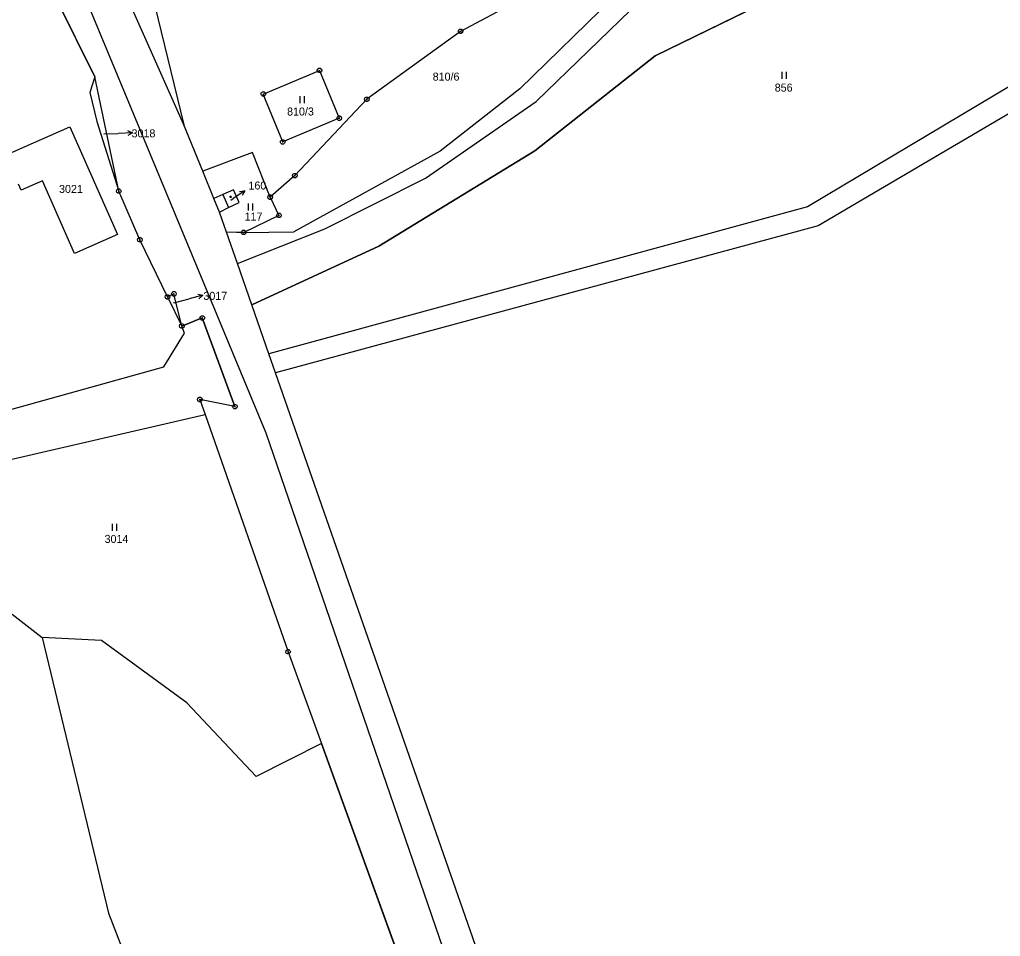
# Model space of a CAD drawing. Extents: x -580551 to -575069, y -1073031 to -1067931.
# Drawn here: x -578349.8 to -578141.5, y -1072489.2 to -1072294.4 of the extents above; entities that cross this region are included whole.
import ezdxf

# ---------------------------------------------------------------- set-up
doc = ezdxf.new("R2010")
doc.units = 0
for name, color, linetype in [('Druh pozemku', 7, 'Continuous'), ('Geodetické body', 7, 'Continuous'), ('Hranice okresů', 7, 'Continuous'), ('Hranice z DKM', 7, 'Continuous'), ('Parcela', 7, 'Continuous'), ('Parcelní číslo', 7, 'Continuous'), ('Parcelní číslo_stavba', 7, 'Continuous'), ('Pomocná vrstva', 7, 'Continuous'), ('Vnitřní kresba', 7, 'Continuous'), ('Vrstva 6', 7, 'Continuous')]:
    doc.layers.add(name, color=color, linetype=linetype)

msp = doc.modelspace()

# ---------------------------------------------------------------- linework, layer by layer
at = {"layer": 'Druh pozemku'}
for p, q in [((-578187.95, -1072305.54), (-578187.95, -1072307.04)), ((-578186.95, -1072307.04), (-578186.95, -1072305.54)), ((-578290.29, -1072310.71), (-578290.29, -1072312.21)), ((-578289.29, -1072312.21), (-578289.29, -1072310.71)), ((-578301.28, -1072333.5), (-578301.28, -1072335)), ((-578300.28, -1072335), (-578300.28, -1072333.5)), ((-578330.18, -1072401.54), (-578330.18, -1072403.04)), ((-578329.18, -1072403.04), (-578329.18, -1072401.54))]:
    msp.add_line(p, q, dxfattribs=at)
msp.add_lwpolyline([(-578304.93, -1072331.94), (-578304.84, -1072332.09), (-578304.93, -1072332.24), (-578305.11, -1072332.24), (-578305.2, -1072332.09), (-578305.11, -1072331.94)], close=True, dxfattribs=at)
at = {"layer": 'Geodetické body'}
for p, q in [((-578256.28, -1072296.93), (-578256.04, -1072296.93)), ((-578286.24, -1072305.23), (-578286, -1072305.23)), ((-578298.18, -1072310.24), (-578297.94, -1072310.24)), ((-578276.19, -1072311.36), (-578275.95, -1072311.36)), ((-578282.05, -1072315.39), (-578281.81, -1072315.39)), ((-578294.06, -1072320.43), (-578293.82, -1072320.43)), ((-578291.48, -1072327.58), (-578291.24, -1072327.58)), ((-578328.89, -1072330.86), (-578328.65, -1072330.86)), ((-578296.72, -1072332.16), (-578296.48, -1072332.16)), ((-578294.86, -1072336.04), (-578294.62, -1072336.04)), ((-578302.35, -1072339.64), (-578302.11, -1072339.64)), ((-578324.4, -1072341.2), (-578324.16, -1072341.2)), ((-578318.52, -1072353.35), (-578318.28, -1072353.35)), ((-578317.16, -1072352.7), (-578316.92, -1072352.7)), ((-578315.47, -1072359.53), (-578315.23, -1072359.53)), ((-578311.14, -1072357.81), (-578310.9, -1072357.81)), ((-578311.66, -1072375.14), (-578311.42, -1072375.14)), ((-578304.21, -1072376.65), (-578303.97, -1072376.65)), ((-578292.92, -1072428.72), (-578292.68, -1072428.72))]:
    msp.add_line(p, q, dxfattribs=at)
for points in [[(-578256.01, -1072296.45), (-578255.76, -1072296.63), (-578255.66, -1072296.92), (-578255.76, -1072297.21), (-578256.01, -1072297.39), (-578256.32, -1072297.39), (-578256.57, -1072297.21), (-578256.67, -1072296.92), (-578256.57, -1072296.63), (-578256.32, -1072296.45)], [(-578285.97, -1072304.75), (-578285.72, -1072304.93), (-578285.62, -1072305.22), (-578285.72, -1072305.51), (-578285.97, -1072305.69), (-578286.28, -1072305.69), (-578286.53, -1072305.51), (-578286.63, -1072305.22), (-578286.53, -1072304.93), (-578286.28, -1072304.75)], [(-578297.91, -1072309.76), (-578297.66, -1072309.94), (-578297.56, -1072310.23), (-578297.66, -1072310.52), (-578297.91, -1072310.7), (-578298.22, -1072310.7), (-578298.47, -1072310.52), (-578298.57, -1072310.23), (-578298.47, -1072309.94), (-578298.22, -1072309.76)], [(-578275.92, -1072310.88), (-578275.67, -1072311.06), (-578275.57, -1072311.35), (-578275.67, -1072311.64), (-578275.92, -1072311.82), (-578276.23, -1072311.82), (-578276.48, -1072311.64), (-578276.58, -1072311.35), (-578276.48, -1072311.06), (-578276.23, -1072310.88)], [(-578281.78, -1072314.91), (-578281.53, -1072315.09), (-578281.43, -1072315.38), (-578281.53, -1072315.67), (-578281.78, -1072315.85), (-578282.09, -1072315.85), (-578282.34, -1072315.67), (-578282.44, -1072315.38), (-578282.34, -1072315.09), (-578282.09, -1072314.91)], [(-578293.79, -1072319.95), (-578293.54, -1072320.13), (-578293.44, -1072320.42), (-578293.54, -1072320.71), (-578293.79, -1072320.89), (-578294.1, -1072320.89), (-578294.35, -1072320.71), (-578294.45, -1072320.42), (-578294.35, -1072320.13), (-578294.1, -1072319.95)], [(-578291.21, -1072327.1), (-578290.96, -1072327.28), (-578290.86, -1072327.57), (-578290.96, -1072327.86), (-578291.21, -1072328.04), (-578291.52, -1072328.04), (-578291.77, -1072327.86), (-578291.87, -1072327.57), (-578291.77, -1072327.28), (-578291.52, -1072327.1)], [(-578328.62, -1072330.38), (-578328.37, -1072330.56), (-578328.27, -1072330.85), (-578328.37, -1072331.14), (-578328.62, -1072331.32), (-578328.93, -1072331.32), (-578329.18, -1072331.14), (-578329.28, -1072330.85), (-578329.18, -1072330.56), (-578328.93, -1072330.38)], [(-578296.45, -1072331.68), (-578296.2, -1072331.86), (-578296.1, -1072332.15), (-578296.2, -1072332.44), (-578296.45, -1072332.62), (-578296.76, -1072332.62), (-578297.01, -1072332.44), (-578297.11, -1072332.15), (-578297.01, -1072331.86), (-578296.76, -1072331.68)], [(-578294.59, -1072335.56), (-578294.34, -1072335.74), (-578294.24, -1072336.03), (-578294.34, -1072336.32), (-578294.59, -1072336.5), (-578294.9, -1072336.5), (-578295.15, -1072336.32), (-578295.25, -1072336.03), (-578295.15, -1072335.74), (-578294.9, -1072335.56)], [(-578324.13, -1072340.72), (-578323.88, -1072340.9), (-578323.78, -1072341.19), (-578323.88, -1072341.48), (-578324.13, -1072341.66), (-578324.44, -1072341.66), (-578324.69, -1072341.48), (-578324.79, -1072341.19), (-578324.69, -1072340.9), (-578324.44, -1072340.72)], [(-578302.08, -1072339.16), (-578301.83, -1072339.34), (-578301.73, -1072339.63), (-578301.83, -1072339.92), (-578302.08, -1072340.1), (-578302.39, -1072340.1), (-578302.64, -1072339.92), (-578302.74, -1072339.63), (-578302.64, -1072339.34), (-578302.39, -1072339.16)], [(-578318.25, -1072352.87), (-578318, -1072353.05), (-578317.9, -1072353.34), (-578318, -1072353.63), (-578318.25, -1072353.81), (-578318.56, -1072353.81), (-578318.81, -1072353.63), (-578318.91, -1072353.34), (-578318.81, -1072353.05), (-578318.56, -1072352.87)], [(-578316.89, -1072352.22), (-578316.64, -1072352.4), (-578316.54, -1072352.69), (-578316.64, -1072352.98), (-578316.89, -1072353.16), (-578317.2, -1072353.16), (-578317.45, -1072352.98), (-578317.55, -1072352.69), (-578317.45, -1072352.4), (-578317.2, -1072352.22)], [(-578310.87, -1072357.33), (-578310.62, -1072357.51), (-578310.52, -1072357.8), (-578310.62, -1072358.09), (-578310.87, -1072358.27), (-578311.18, -1072358.27), (-578311.43, -1072358.09), (-578311.53, -1072357.8), (-578311.43, -1072357.51), (-578311.18, -1072357.33)], [(-578315.2, -1072359.05), (-578314.95, -1072359.23), (-578314.85, -1072359.52), (-578314.95, -1072359.81), (-578315.2, -1072359.99), (-578315.51, -1072359.99), (-578315.76, -1072359.81), (-578315.86, -1072359.52), (-578315.76, -1072359.23), (-578315.51, -1072359.05)], [(-578311.39, -1072374.66), (-578311.14, -1072374.84), (-578311.04, -1072375.13), (-578311.14, -1072375.42), (-578311.39, -1072375.6), (-578311.7, -1072375.6), (-578311.95, -1072375.42), (-578312.05, -1072375.13), (-578311.95, -1072374.84), (-578311.7, -1072374.66)], [(-578303.94, -1072376.17), (-578303.69, -1072376.35), (-578303.59, -1072376.64), (-578303.69, -1072376.93), (-578303.94, -1072377.11), (-578304.25, -1072377.11), (-578304.5, -1072376.93), (-578304.6, -1072376.64), (-578304.5, -1072376.35), (-578304.25, -1072376.17)], [(-578292.65, -1072428.24), (-578292.4, -1072428.42), (-578292.3, -1072428.71), (-578292.4, -1072429), (-578292.65, -1072429.18), (-578292.96, -1072429.18), (-578293.21, -1072429), (-578293.31, -1072428.71), (-578293.21, -1072428.42), (-578292.96, -1072428.24)]]:
    msp.add_lwpolyline(points, close=True, dxfattribs=at)
at = {"layer": 'Hranice okresů'}
for points in [[(-578328.77, -1072330.86), (-578333.88, -1072306.58), (-578349.6, -1072274.81), (-578373.44, -1072284.96), (-578412.74, -1072301.69), (-578418.98, -1072304.35), (-578421.46, -1072289.64), (-578423.21, -1072279.21), (-578426.43, -1072275.55), (-578429.77, -1072292.43), (-578431.03, -1072298.81), (-578439.43, -1072329.32)], [(-578304.09, -1072376.65), (-578311.02, -1072357.81), (-578315.35, -1072359.53), (-578317.04, -1072352.7), (-578318.4, -1072353.35), (-578324.28, -1072341.2), (-578328.77, -1072330.86)], [(-578304.09, -1072376.65), (-578311.54, -1072375.14), (-578310.43, -1072378.3), (-578292.8, -1072428.72), (-578285.74, -1072448.17), (-578258.57, -1072522.96), (-578243.29, -1072548.82), (-578234.82, -1072561.67), (-578182.02, -1072625.12), (-578152.3, -1072657.58)]]:
    msp.add_lwpolyline(points, dxfattribs=at)
at = {"layer": 'Hranice z DKM'}
msp.add_lwpolyline([(-578300.5, -1072355.03), (-578273.54, -1072342.55), (-578240.36, -1072322.29), (-578214.81, -1072302.14), (-578176.47, -1072283.37), (-578161.43, -1072271.67), (-578128.77, -1072260.78)], dxfattribs=at)
at = {"layer": 'Parcela'}
for p, q in [((-578314.93, -1072316.8), (-578336.75, -1072267.72)), ((-578349.6, -1072274.81), (-578333.88, -1072306.58)), ((-578176.47, -1072283.37), (-578214.81, -1072302.14)), ((-578243.57, -1072309.11), (-578220.98, -1072287.09)), ((-578244.05, -1072290.52), (-578256.16, -1072296.93)), ((-578240.12, -1072311.83), (-578217.85, -1072290.22)), ((-578321.12, -1072291.52), (-578314.93, -1072316.8)), ((-578256.16, -1072296.93), (-578276.07, -1072311.36)), ((-578214.81, -1072302.14), (-578240.36, -1072322.29)), ((-578298.06, -1072310.24), (-578286.12, -1072305.23)), ((-578286.12, -1072305.23), (-578281.93, -1072315.39)), ((-578333.88, -1072306.58), (-578334.9, -1072309.95)), ((-578328.77, -1072330.86), (-578333.88, -1072306.58)), ((-578243.57, -1072309.11), (-578260.52, -1072322.39)), ((-578138.98, -1072308.3), (-578182.47, -1072334.23)), ((-578334.9, -1072309.95), (-578333.41, -1072316.09)), ((-578293.94, -1072320.43), (-578298.06, -1072310.24)), ((-578276.07, -1072311.36), (-578291.36, -1072327.58)), ((-578263.61, -1072328.14), (-578240.12, -1072311.83)), ((-578136.25, -1072312.34), (-578180.23, -1072338.25)), ((-578281.93, -1072315.39), (-578293.94, -1072320.43)), ((-578352.79, -1072323.26), (-578339.13, -1072317.2)), ((-578339.13, -1072317.2), (-578329, -1072340.07)), ((-578333.41, -1072316.09), (-578328.77, -1072330.86)), ((-578310.92, -1072326.64), (-578314.93, -1072316.8)), ((-578240.36, -1072322.29), (-578273.54, -1072342.55)), ((-578260.52, -1072322.39), (-578291.56, -1072339.54)), ((-578308.57, -1072332.41), (-578310.92, -1072326.64)), ((-578291.36, -1072327.58), (-578296.6, -1072332.16)), ((-578285.01, -1072338.88), (-578263.61, -1072328.14)), ((-578349.5, -1072330.66), (-578350.05, -1072329.39)), ((-578344.94, -1072328.65), (-578349.5, -1072330.66)), ((-578338.15, -1072344.12), (-578344.94, -1072328.65)), ((-578304.43, -1072330.59), (-578306.68, -1072331.58)), ((-578303.21, -1072333.31), (-578304.43, -1072330.59)), ((-578324.28, -1072341.2), (-578328.77, -1072330.86)), ((-578306.68, -1072331.58), (-578308.57, -1072332.41)), ((-578307.39, -1072335.31), (-578308.57, -1072332.41)), ((-578296.6, -1072332.16), (-578294.74, -1072336.04)), ((-578307.39, -1072335.31), (-578305.48, -1072334.33)), ((-578305.48, -1072334.33), (-578303.21, -1072333.31)), ((-578182.47, -1072334.23), (-578296.86, -1072365.46)), ((-578305.89, -1072339.61), (-578307.39, -1072335.31)), ((-578294.74, -1072336.04), (-578302.23, -1072339.64)), ((-578303.57, -1072346.25), (-578285.01, -1072338.88)), ((-578180.23, -1072338.25), (-578295.47, -1072369.44)), ((-578329, -1072340.07), (-578338.15, -1072344.12)), ((-578303.77, -1072339.65), (-578305.89, -1072339.61)), ((-578303.57, -1072346.25), (-578305.89, -1072339.61)), ((-578302.23, -1072339.64), (-578303.77, -1072339.65)), ((-578302.23, -1072339.64), (-578291.56, -1072339.54)), ((-578318.4, -1072353.35), (-578324.28, -1072341.2)), ((-578273.54, -1072342.55), (-578300.5, -1072355.03)), ((-578300.5, -1072355.03), (-578303.57, -1072346.25)), ((-578317.04, -1072352.7), (-578318.4, -1072353.35)), ((-578318.4, -1072353.35), (-578315.35, -1072359.53)), ((-578315.35, -1072359.53), (-578317.04, -1072352.7)), ((-578296.86, -1072365.46), (-578300.5, -1072355.03)), ((-578315.35, -1072359.53), (-578311.02, -1072357.81)), ((-578314.82, -1072361.04), (-578315.35, -1072359.53)), ((-578311.02, -1072357.81), (-578304.09, -1072376.65)), ((-578319.16, -1072368.22), (-578314.82, -1072361.04)), ((-578295.47, -1072369.44), (-578296.86, -1072365.46)), ((-578388.04, -1072387.29), (-578319.16, -1072368.22)), ((-578238.25, -1072533.37), (-578295.47, -1072369.44)), ((-578311.54, -1072375.14), (-578310.43, -1072378.3)), ((-578304.09, -1072376.65), (-578311.54, -1072375.14)), ((-578367.5, -1072391.52), (-578310.43, -1072378.3)), ((-578310.43, -1072378.3), (-578292.8, -1072428.72)), ((-578351.38, -1072420.7), (-578345.04, -1072425.7)), ((-578345.04, -1072425.7), (-578330.92, -1072484.2)), ((-578332.42, -1072426.32), (-578345.04, -1072425.7)), ((-578314.34, -1072439.57), (-578332.42, -1072426.32)), ((-578292.8, -1072428.72), (-578285.74, -1072448.17)), ((-578299.61, -1072455.2), (-578314.34, -1072439.57)), ((-578285.74, -1072448.17), (-578299.61, -1072455.2)), ((-578258.57, -1072522.96), (-578285.74, -1072448.17)), ((-578330.92, -1072484.2), (-578304.28, -1072553.73))]:
    msp.add_line(p, q, dxfattribs=at)
at = {"layer": 'Parcelní číslo'}
msp.add_lwpolyline([(-578396.984, -1071513.081), (-578392.613, -1071573.689), (-578385.634, -1071670.478), (-578375.02, -1071771.171), (-578374.791, -1071827.387), (-578382.128, -1071854.922), (-578394.511, -1071889.799), (-578400.532, -1071906.757), (-578409.416, -1071923.758), (-578413.314, -1071938.214), (-578421.881, -1071969.98), (-578424.092, -1071997.413), (-578426.02, -1072021.331), (-578421.799, -1072054.547), (-578413.085, -1072096.996), (-578402.044, -1072150.781), (-578372.039, -1072212.641), (-578343.339, -1072271.808), (-578297.514, -1072382.207), (-578259.907, -1072491.657)], dxfattribs=at)
at = {"layer": 'Pomocná vrstva'}
for p, q in [((-578331.95, -1072318.72), (-578328.88, -1072318.6)), ((-578325.882, -1072318.484), (-578328.88, -1072318.6)), ((-578304.98, -1072332.76), (-578304.49, -1072332.44)), ((-578301.978, -1072330.799), (-578304.49, -1072332.44)), ((-578310.887, -1072352.991), (-578313.79, -1072353.75)), ((-578317.04, -1072354.6), (-578313.79, -1072353.75))]:
    msp.add_line(p, q, dxfattribs=at)
for points in [[(-578326.901, -1072318.023), (-578325.882, -1072318.484), (-578326.862, -1072319.022)], [(-578303.089, -1072330.928), (-578301.978, -1072330.799), (-578302.542, -1072331.765)], [(-578311.981, -1072352.761), (-578310.887, -1072352.991), (-578311.729, -1072353.728)]]:
    msp.add_lwpolyline(points, dxfattribs=at)
at = {"layer": 'Vnitřní kresba'}
msp.add_line((-578306.68, -1072331.58), (-578305.48, -1072334.33), dxfattribs=at)
at = {"layer": 'Vrstva 6'}
for p, q in [((-578300.39, -1072322.64), (-578310.92, -1072326.64)), ((-578296.6, -1072332.16), (-578300.39, -1072322.64))]:
    msp.add_line(p, q, dxfattribs=at)

# ---------------------------------------------------------------- texts
at = {"layer": 'Parcelní číslo'}
for s, height, p in [('810/6', 1.7, (-578262.089, -1072307.4)), ('856', 1.7, (-578189.439, -1072309.73)), ('810/3', 1.7, (-578293.016, -1072314.81)), ('3018', 0.17, (-578332.193, -1072318.805)), ('3021', 1.7, (-578341.451, -1072331.26)), ('117', 1.7, (-578302.045, -1072337.12)), ('3017', 0.17, (-578317.277, -1072354.685)), ('3014', 1.7, (-578331.776, -1072405.59))]:
    msp.add_text(s, height=height, dxfattribs=at).set_placement(p)
at = {"layer": 'Parcelní číslo_stavba'}
msp.add_text('160', height=0.1, dxfattribs=at).set_placement((-578305.076, -1072332.76))
at = {"layer": 'Pomocná vrstva'}
for s, p in [('3018', (-578326.044, -1072319.45)), ('160', (-578301.217, -1072330.53)), ('3017', (-578310.79, -1072353.96))]:
    msp.add_text(s, height=1.7, dxfattribs=at).set_placement(p)

doc.saveas('drawing.dxf')
